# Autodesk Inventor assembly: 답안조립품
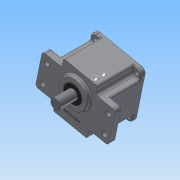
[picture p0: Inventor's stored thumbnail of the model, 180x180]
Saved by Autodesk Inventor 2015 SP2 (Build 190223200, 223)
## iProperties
Created: 2015-06
Part Number: 답안조립품
Document SubType Name: Assembly
Designer: AMC
Author: AMC
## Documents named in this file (12)
- C:\Users\AMC\Desktop\450620V1016\답안조립품.iam
- C:\Users\AMC\Desktop\450620V1016\본체.ipt
- C:\Users\AMC\Desktop\450620V1016\베어링 608.ipt
- 베어링 608.ipt
- C:\Users\AMC\Desktop\450620V1016\베어링 6003.ipt
- 베어링 6003.ipt
- C:\Users\AMC\Desktop\450620V1016\오일실 8x22x7.ipt
- C:\Users\AMC\Desktop\450620V1016\메인축.ipt
- C:\Users\AMC\Desktop\450620V1016\서브축.ipt
- C:\Users\AMC\Desktop\450620V1016\커버.ipt
- C:\Users\AMC\Desktop\450620V1016\오일실 17x32x8.ipt
- C:\Users\AMC\Desktop\450620V1016\M4x0.5x16.ipt
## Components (4 placed, 1 different names)
1. M4x0.5x12:1
2. M4x0.5x12:2
3. M4x0.5x12:3
4. M4x0.5x12:4
